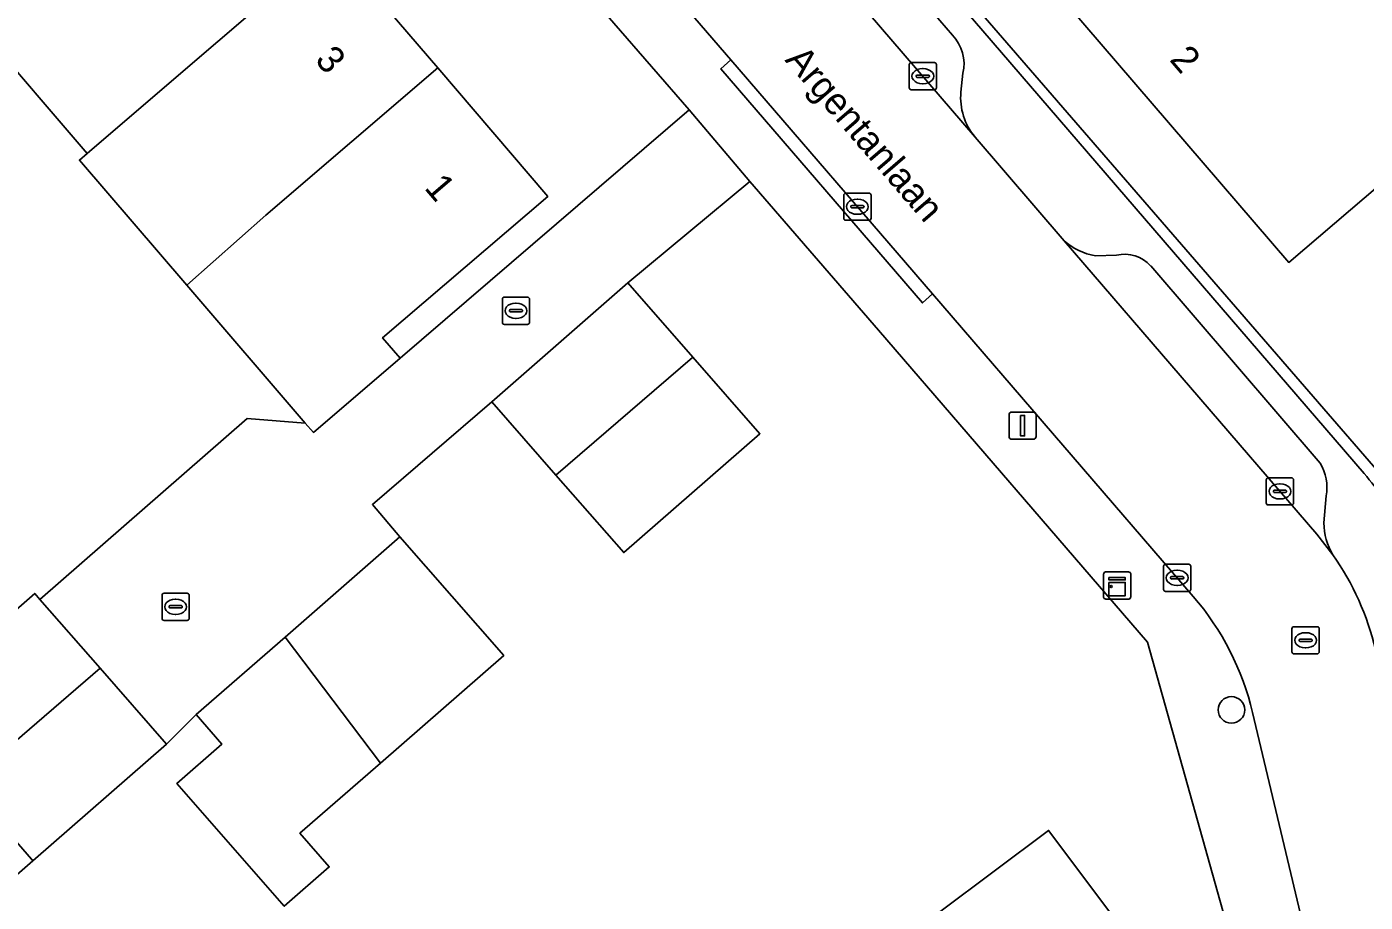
# Model space of a CAD drawing. Extents: x 158472 to 159562, y 388525 to 389606.
# Drawn here: x 159119.07 to 159168.29, y 388962.68 to 388994.9 of the extents above; entities that cross this region are included whole.
import ezdxf

# ---------------------------------------------------------------- set-up
doc = ezdxf.new("R2010")
doc.units = 0
for name, color, linetype in [('IMGEO_Boom', 7, 'Continuous'), ('IMGEO_Erf', 7, 'Continuous'), ('IMGEO_Groenvoorziening', 7, 'Continuous'), ('IMGEO_Kast', 7, 'Continuous'), ('IMGEO_Kolk', 7, 'Continuous'), ('IMGEO_Lichtmast', 7, 'Continuous'), ('IMGEO_Muur', 7, 'Continuous'), ('IMGEO_Openbare_ruimte_label', 7, 'Continuous'), ('IMGEO_Pand', 7, 'Continuous'), ('IMGEO_Pand_nummerreeks', 7, 'Continuous'), ('IMGEO_Parkeervlak_open', 7, 'Continuous'), ('IMGEO_Rijbaan_lokaal_open', 7, 'Continuous'), ('IMGEO_Rioolput', 7, 'Continuous'), ('IMGEO_Voetpad_open', 7, 'Continuous')]:
    doc.layers.add(name, color=color, linetype=linetype)

msp = doc.modelspace()

# ---------------------------------------------------------------- linework, layer by layer
at = {"layer": 'IMGEO_Boom'}
msp.add_circle((159163.368, 388969.761), 0.489, dxfattribs=at)
at = {"layer": 'IMGEO_Erf'}
for points in [[(159118.567, 389011.629), (159120.859, 389008.951), (159122.471, 389007.068), (159124.172, 389005.081), (159126.372, 389002.51), (159128.521, 389000), (159128.666, 388999.83), (159130.274, 388997.952), (159131.979, 388995.96), (159134.177, 388993.391), (159138.228, 388988.659), (159132.151, 388983.457), (159132.794, 388982.706), (159143.43, 388991.84), (159136.496, 388999.827), (159136.348, 389000), (159133.184, 389003.697), (159128.667, 389008.929), (159125.355, 389012.799), (159120.867, 389018.029), (159119.175, 389020.005)], [(159114.455, 388969.768), (159119.356, 388974.048), (159119.547, 388973.829), (159127.165, 388980.484), (159129.309, 388980.318), (159124.951, 388985.395), (159121.003, 388989.994), (159121.284, 388990.235), (159117.383, 388994.78)], [(159164.945, 388955.64), (159162.862, 388963.067), (159160.285, 388972.252), (159150.387, 388983.731), (159145.661, 388989.212), (159141.174, 388985.475), (159143.562, 388982.741), (159146.025, 388979.921), (159141.02, 388975.55), (159138.527, 388978.405), (159136.169, 388981.104), (159131.778, 388977.318), (159132.791, 388976.129), (159136.604, 388971.764), (159132.069, 388967.803), (159129.112, 388965.22), (159130.191, 388963.985), (159128.535, 388962.538), (159124.587, 388967.056), (159126.243, 388968.503), (159125.295, 388969.587), (159124.199, 388968.503), (159119.287, 388964.213), (159114.314, 388959.869)], [(159152.647, 388962.327), (159156.646, 388965.327), (159161.636, 388958.674)]]:
    msp.add_lwpolyline(points, dxfattribs=at)
at = {"layer": 'IMGEO_Groenvoorziening'}
for points in [[(159153.445, 388996.248), (159153.16, 388996.004), (159168.248, 388978.456)], [(159169.627, 388976.586), (159170.096, 388976.988), (159153.445, 388996.248)]]:
    msp.add_lwpolyline(points, dxfattribs=at)
msp.add_arc((159156.207, 388968.133), 15.861, 32.2058, 40.6068, dxfattribs=at)
at = {"layer": 'IMGEO_Kast'}
for p, q in [((159158.666, 388973.914), (159158.666, 388974.755)), ((159158.666, 388974.755), (159158.666, 388973.914)), ((159158.741, 388974.839), (159159.582, 388974.839)), ((159159.582, 388974.839), (159158.741, 388974.839)), ((159159.666, 388974.764), (159159.666, 388973.923)), ((159159.666, 388973.923), (159159.666, 388974.764)), ((159159.591, 388973.839), (159158.75, 388973.839)), ((159158.75, 388973.839), (159159.591, 388973.839))]:
    msp.add_line(p, q, dxfattribs=at)
for points in [[(159158.861, 388974.629), (159159.461, 388974.629), (159159.461, 388974.544), (159158.861, 388974.544), (159158.861, 388974.629)], [(159158.861, 388974.454), (159159.461, 388974.454), (159159.461, 388973.965), (159158.861, 388973.965), (159158.861, 388974.454)]]:
    msp.add_lwpolyline(points, dxfattribs=at)
msp.add_circle((159158.945, 388974.303), 0.0377, dxfattribs=at)
for centre, start, end in [((159158.744, 388974.761), 92.4484, 184.2845), ((159158.744, 388974.761), 92.4484, 184.2845), ((159159.588, 388974.761), 2.4484, 94.2845), ((159159.588, 388974.761), 2.4484, 94.2845), ((159158.744, 388973.917), 182.4484, 274.2845), ((159158.744, 388973.917), 182.4484, 274.2845), ((159159.588, 388973.917), 272.4484, 4.2845), ((159159.588, 388973.917), 272.4484, 4.2845)]:
    msp.add_arc(centre, 0.0779, start, end, dxfattribs=at)
at = {"layer": 'IMGEO_Kolk'}
for p, q in [((159151.519, 388992.654), (159151.519, 388993.506)), ((159151.594, 388993.58), (159152.446, 388993.58)), ((159152.007, 388993.36), (159152.032, 388993.36)), ((159152.52, 388993.506), (159152.52, 388992.654)), ((159151.778, 388993.074), (159151.778, 388993.086)), ((159152.216, 388993.037), (159151.818, 388993.037)), ((159151.821, 388993.123), (159152.219, 388993.123)), ((159152.03, 388992.8), (159152.005, 388992.8)), ((159152.262, 388993.086), (159152.262, 388993.074)), ((159152.446, 388992.58), (159151.594, 388992.58)), ((159149.113, 388987.853), (159149.113, 388988.705)), ((159149.188, 388988.779), (159150.04, 388988.779)), ((159149.415, 388988.322), (159149.813, 388988.322)), ((159149.601, 388988.559), (159149.626, 388988.559)), ((159150.114, 388988.705), (159150.114, 388987.853)), ((159149.372, 388988.273), (159149.372, 388988.285)), ((159149.81, 388988.236), (159149.412, 388988.236)), ((159149.624, 388987.999), (159149.599, 388987.999)), ((159149.856, 388988.285), (159149.856, 388988.273)), ((159150.04, 388987.779), (159149.188, 388987.779)), ((159136.555, 388984.024), (159136.555, 388984.876)), ((159136.63, 388984.95), (159137.482, 388984.95)), ((159137.556, 388984.876), (159137.556, 388984.024)), ((159136.814, 388984.444), (159136.814, 388984.456)), ((159137.252, 388984.407), (159136.854, 388984.407)), ((159136.857, 388984.493), (159137.255, 388984.493)), ((159137.043, 388984.73), (159137.068, 388984.73)), ((159137.298, 388984.456), (159137.298, 388984.444)), ((159137.482, 388983.95), (159136.63, 388983.95)), ((159137.066, 388984.17), (159137.041, 388984.17)), ((159164.651, 388977.377), (159164.651, 388978.229)), ((159164.726, 388978.303), (159165.578, 388978.303)), ((159165.139, 388978.083), (159165.164, 388978.083)), ((159165.652, 388978.229), (159165.652, 388977.377)), ((159164.91, 388977.797), (159164.91, 388977.809)), ((159165.348, 388977.76), (159164.95, 388977.76)), ((159164.953, 388977.846), (159165.351, 388977.846)), ((159165.162, 388977.523), (159165.137, 388977.523)), ((159165.394, 388977.809), (159165.394, 388977.797)), ((159165.578, 388977.303), (159164.726, 388977.303)), ((159160.872, 388974.196), (159160.872, 388975.048)), ((159160.947, 388975.122), (159161.799, 388975.122)), ((159161.873, 388975.048), (159161.873, 388974.196)), ((159161.131, 388974.616), (159161.131, 388974.628)), ((159161.569, 388974.579), (159161.171, 388974.579)), ((159161.174, 388974.665), (159161.572, 388974.665)), ((159161.36, 388974.902), (159161.385, 388974.902)), ((159161.615, 388974.628), (159161.615, 388974.616)), ((159124.114, 388974.056), (159124.966, 388974.056)), ((159161.799, 388974.122), (159160.947, 388974.122)), ((159161.383, 388974.342), (159161.358, 388974.342)), ((159124.039, 388973.13), (159124.039, 388973.982)), ((159124.298, 388973.55), (159124.298, 388973.562)), ((159124.341, 388973.599), (159124.739, 388973.599)), ((159124.527, 388973.836), (159124.552, 388973.836)), ((159124.782, 388973.562), (159124.782, 388973.55)), ((159125.04, 388973.982), (159125.04, 388973.13)), ((159124.966, 388973.056), (159124.114, 388973.056)), ((159124.736, 388973.513), (159124.338, 388973.513)), ((159124.55, 388973.276), (159124.525, 388973.276))]:
    msp.add_line(p, q, dxfattribs=at)
for points in [[(159151.519, 388992.654), (159151.519, 388993.506)], [(159151.594, 388993.58), (159152.446, 388993.58)], [(159152.52, 388993.506), (159152.52, 388992.654)], [(159152.446, 388992.58), (159151.594, 388992.58)], [(159149.113, 388987.853), (159149.113, 388988.705)], [(159149.188, 388988.779), (159150.04, 388988.779)], [(159150.114, 388988.705), (159150.114, 388987.853)], [(159150.04, 388987.779), (159149.188, 388987.779)], [(159136.555, 388984.024), (159136.555, 388984.876)], [(159136.63, 388984.95), (159137.482, 388984.95)], [(159137.556, 388984.876), (159137.556, 388984.024)], [(159137.482, 388983.95), (159136.63, 388983.95)], [(159164.651, 388977.377), (159164.651, 388978.229)], [(159164.726, 388978.303), (159165.578, 388978.303)], [(159165.652, 388978.229), (159165.652, 388977.377)], [(159165.578, 388977.303), (159164.726, 388977.303)], [(159160.872, 388974.196), (159160.872, 388975.048)], [(159160.947, 388975.122), (159161.799, 388975.122)], [(159161.873, 388975.048), (159161.873, 388974.196)], [(159124.114, 388974.056), (159124.966, 388974.056)], [(159161.799, 388974.122), (159160.947, 388974.122)], [(159124.039, 388973.13), (159124.039, 388973.982)], [(159125.04, 388973.982), (159125.04, 388973.13)], [(159124.966, 388973.056), (159124.114, 388973.056)]]:
    msp.add_lwpolyline(points, dxfattribs=at)
for centre, radius, start, end in [((159151.596, 388993.504), 0.0765, 91.552, 178.448), ((159151.596, 388993.504), 0.0765, 91.552, 178.448), ((159152.444, 388993.504), 0.0765, 1.552, 88.448), ((159152.444, 388993.504), 0.0765, 1.552, 88.448), ((159151.818, 388993.083), 0.0403, 85.8775, 175.7526), ((159151.815, 388993.073), 0.0366, 178.938, 274.7102), ((159152.219, 388993.08), 0.043, 264.8664, 352.4533), ((159152.223, 388993.085), 0.0386, 1.7309, 96.639), ((159151.596, 388992.656), 0.0765, 181.552, 268.448), ((159151.596, 388992.656), 0.0765, 181.552, 268.448), ((159152.444, 388992.656), 0.0765, 271.552, 358.448), ((159152.444, 388992.656), 0.0765, 271.552, 358.448), ((159149.19, 388988.703), 0.0765, 91.552, 178.448), ((159149.19, 388988.703), 0.0765, 91.552, 178.448), ((159149.412, 388988.282), 0.0403, 85.8775, 175.7526), ((159149.817, 388988.284), 0.0386, 1.7309, 96.639), ((159150.038, 388988.703), 0.0765, 1.552, 88.448), ((159150.038, 388988.703), 0.0765, 1.552, 88.448), ((159149.19, 388987.855), 0.0765, 181.552, 268.448), ((159149.19, 388987.855), 0.0765, 181.552, 268.448), ((159149.409, 388988.272), 0.0366, 178.938, 274.7102), ((159149.813, 388988.279), 0.043, 264.8664, 352.4533), ((159150.038, 388987.855), 0.0765, 271.552, 358.448), ((159150.038, 388987.855), 0.0765, 271.552, 358.448), ((159136.632, 388984.874), 0.0765, 91.552, 178.448), ((159136.632, 388984.874), 0.0765, 91.552, 178.448), ((159137.48, 388984.874), 0.0765, 1.552, 88.448), ((159137.48, 388984.874), 0.0765, 1.552, 88.448), ((159136.854, 388984.453), 0.0403, 85.8775, 175.7526), ((159136.851, 388984.443), 0.0366, 178.938, 274.7102), ((159137.255, 388984.45), 0.043, 264.8664, 352.4533), ((159137.259, 388984.455), 0.0386, 1.7309, 96.639), ((159136.632, 388984.026), 0.0765, 181.552, 268.448), ((159136.632, 388984.026), 0.0765, 181.552, 268.448), ((159137.48, 388984.026), 0.0765, 271.552, 358.448), ((159137.48, 388984.026), 0.0765, 271.552, 358.448), ((159164.728, 388978.227), 0.0765, 91.552, 178.448), ((159164.728, 388978.227), 0.0765, 91.552, 178.448), ((159165.576, 388978.227), 0.0765, 1.552, 88.448), ((159165.576, 388978.227), 0.0765, 1.552, 88.448), ((159164.95, 388977.806), 0.0403, 85.8775, 175.7526), ((159164.947, 388977.796), 0.0366, 178.938, 274.7102), ((159165.351, 388977.803), 0.043, 264.8664, 352.4533), ((159165.355, 388977.808), 0.0386, 1.7309, 96.639), ((159164.728, 388977.379), 0.0765, 181.552, 268.448), ((159164.728, 388977.379), 0.0765, 181.552, 268.448), ((159165.576, 388977.379), 0.0765, 271.552, 358.448), ((159165.576, 388977.379), 0.0765, 271.552, 358.448), ((159160.949, 388975.046), 0.0765, 91.552, 178.448), ((159160.949, 388975.046), 0.0765, 91.552, 178.448), ((159161.797, 388975.046), 0.0765, 1.552, 88.448), ((159161.797, 388975.046), 0.0765, 1.552, 88.448), ((159161.171, 388974.625), 0.0403, 85.8775, 175.7526), ((159161.168, 388974.615), 0.0366, 178.938, 274.7102), ((159161.572, 388974.622), 0.043, 264.8664, 352.4533), ((159161.576, 388974.627), 0.0386, 1.7309, 96.639), ((159124.116, 388973.98), 0.0765, 91.552, 178.448), ((159124.116, 388973.98), 0.0765, 91.552, 178.448), ((159124.964, 388973.98), 0.0765, 1.552, 88.448), ((159124.964, 388973.98), 0.0765, 1.552, 88.448), ((159160.949, 388974.198), 0.0765, 181.552, 268.448), ((159160.949, 388974.198), 0.0765, 181.552, 268.448), ((159161.797, 388974.198), 0.0765, 271.552, 358.448), ((159161.797, 388974.198), 0.0765, 271.552, 358.448), ((159124.338, 388973.559), 0.0403, 85.8775, 175.7526), ((159124.335, 388973.549), 0.0366, 178.938, 274.7102), ((159124.739, 388973.556), 0.043, 264.8664, 352.4533), ((159124.743, 388973.561), 0.0386, 1.7309, 96.639), ((159124.116, 388973.132), 0.0765, 181.552, 268.448), ((159124.116, 388973.132), 0.0765, 181.552, 268.448), ((159124.964, 388973.132), 0.0765, 271.552, 358.448), ((159124.964, 388973.132), 0.0765, 271.552, 358.448)]:
    msp.add_arc(centre, radius, start, end, dxfattribs=at)
for centre, major_axis, ratio, start_param, end_param in [((159152.006, 388993.08), (-0.387, 0.002), 0.722429, 4.712389, 7.853982), ((159152.031, 388993.08), (-0.39, 0.002), 0.717154, 1.570796, 4.712389), ((159149.6, 388988.279), (-0.387, 0.002), 0.722429, 4.712389, 7.853982), ((159149.625, 388988.279), (-0.39, 0.002), 0.717154, 1.570796, 4.712389), ((159137.042, 388984.45), (-0.387, 0.002), 0.722429, 4.712389, 7.853982), ((159137.067, 388984.45), (-0.39, 0.002), 0.717154, 1.570796, 4.712389), ((159165.138, 388977.803), (-0.387, 0.002), 0.722429, 4.712389, 7.853982), ((159165.163, 388977.803), (-0.39, 0.002), 0.717154, 1.570796, 4.712389), ((159161.359, 388974.622), (-0.387, 0.002), 0.722429, 4.712389, 7.853982), ((159161.384, 388974.622), (-0.39, 0.002), 0.717154, 1.570796, 4.712389), ((159124.526, 388973.556), (-0.387, 0.002), 0.722429, 4.712389, 7.853982), ((159124.551, 388973.556), (-0.39, 0.002), 0.717154, 1.570796, 4.712389)]:
    msp.add_ellipse(centre, major_axis=major_axis, ratio=ratio, start_param=start_param, end_param=end_param, dxfattribs=at)
at = {"layer": 'IMGEO_Lichtmast'}
for p, q in [((159155.192, 388979.822), (159155.192, 388980.622)), ((159155.192, 388980.622), (159155.192, 388979.822)), ((159155.292, 388980.722), (159156.082, 388980.722)), ((159156.082, 388980.722), (159155.292, 388980.722)), ((159156.182, 388980.622), (159156.182, 388979.822)), ((159156.182, 388979.822), (159156.182, 388980.622)), ((159156.082, 388979.722), (159155.292, 388979.722)), ((159155.292, 388979.722), (159156.082, 388979.722))]:
    msp.add_line(p, q, dxfattribs=at)
msp.add_lwpolyline([(159155.612, 388980.597), (159155.762, 388980.597), (159155.762, 388979.847), (159155.612, 388979.847), (159155.612, 388980.597)], dxfattribs=at)
for centre, start, end in [((159155.292, 388980.622), 90, 180), ((159155.292, 388980.622), 90, 180), ((159156.082, 388980.622), 0, 90), ((159156.082, 388980.622), 360, 90), ((159155.292, 388979.822), 180, 270), ((159155.292, 388979.822), 180, 270), ((159156.082, 388979.822), 270, 0), ((159156.082, 388979.822), 270, 0)]:
    msp.add_arc(centre, 0.1, start, end, dxfattribs=at)
at = {"layer": 'IMGEO_Muur'}
for points in [[(159150.387, 388983.731), (159160.285, 388972.252), (159162.862, 388963.067)], [(159129.309, 388980.318), (159127.165, 388980.484), (159119.547, 388973.829)]]:
    msp.add_lwpolyline(points, dxfattribs=at)
at = {"layer": 'IMGEO_Pand'}
for points in [[(159203.019, 389018.342), (159193.124, 389029.895), (159192.975, 389030.069), (159172.865, 389012.863), (159155.422, 388997.939), (159165.476, 388986.23), (159177.236, 388996.288)], [(159130.274, 388997.952), (159128.666, 388999.83), (159128.521, 389000), (159126.372, 389002.51), (159123.454, 389000), (159120.061, 388997.082), (159117.663, 388995.021), (159117.383, 388994.78), (159121.284, 388990.235), (159123.957, 388992.53)], [(159134.177, 388993.391), (159131.979, 388995.96), (159130.274, 388997.952), (159123.957, 388992.53), (159121.284, 388990.235), (159121.003, 388989.994), (159124.951, 388985.395), (159127.857, 388987.973)], [(159127.857, 388987.973), (159124.951, 388985.395), (159129.309, 388980.318), (159129.608, 388979.97), (159132.794, 388982.706), (159132.151, 388983.457), (159138.228, 388988.659), (159134.177, 388993.391)], [(159138.527, 388978.405), (159143.55, 388982.73), (159143.562, 388982.741), (159141.174, 388985.475), (159136.169, 388981.104)], [(159138.527, 388978.405), (159141.02, 388975.55), (159146.025, 388979.921), (159143.562, 388982.741), (159143.55, 388982.73)], [(159128.564, 388972.44), (159132.069, 388967.803), (159136.604, 388971.764), (159132.791, 388976.129)], [(159114.455, 388969.768), (159116.82, 388967.04), (159121.759, 388971.296), (159119.547, 388973.829), (159119.356, 388974.048)], [(159128.564, 388972.44), (159125.295, 388969.587), (159126.243, 388968.503), (159124.587, 388967.056), (159128.535, 388962.538), (159130.191, 388963.985), (159129.112, 388965.22), (159132.069, 388967.803)], [(159116.82, 388967.04), (159119.24, 388964.27), (159119.287, 388964.213), (159124.199, 388968.503), (159121.759, 388971.296)], [(159116.82, 388967.04), (159111.816, 388962.729), (159114.016, 388960.211), (159114.314, 388959.869), (159119.287, 388964.213), (159119.24, 388964.27)], [(159151.75, 388961.654), (159156.74, 388955.002), (159161.636, 388958.674), (159156.646, 388965.327), (159152.647, 388962.327)]]:
    msp.add_lwpolyline(points, close=True, dxfattribs=at)
at = {"layer": 'IMGEO_Parkeervlak_open'}
for points in [[(159143.71, 389002.747), (159146.071, 389000), (159153.949, 388990.832)], [(159153.106, 388994.586), (159148.455, 389000), (159147.111, 389001.564)], [(159153.42, 388992.498), (159153.493, 388993.192)], [(159157.221, 388987.027), (159166.505, 388976.226), (159167.097, 388975.467)], [(159159.147, 388986.497), (159158.367, 388986.473)], [(159166.636, 388978.847), (159160.399, 388986.103)], [(159166.772, 388976.642), (159166.854, 388977.635)]]:
    msp.add_lwpolyline(points, dxfattribs=at)
for centre, radius, start, end in [((159152.044, 388993.54), 1.49, 346.4825, 44.5488), ((159155.661, 388992.293), 2.251, 174.7642, 220.4679), ((159158.755, 388988.738), 2.298, 228.1198, 260.28), ((159159.432, 388985.218), 1.31, 42.4799, 102.5829), ((159165.049, 388977.936), 1.83, 350.5332, 29.8601), ((159169.062, 388976.643), 2.29, 180.0233, 210.8992)]:
    msp.add_arc(centre, radius, start, end, dxfattribs=at)
at = {"layer": 'IMGEO_Rijbaan_lokaal_open'}
for points in [[(159157.221, 388987.027), (159153.949, 388990.832), (159146.071, 389000), (159143.71, 389002.747), (159140.367, 389006.639), (159130.603, 389018.005), (159126.851, 389022.373), (159123.771, 389025.812), (159121.896, 389024.199), (159120.042, 389022.605), (159120.134, 389022.499), (159123.157, 389018.99), (159126.435, 389015.185), (159131.375, 389009.452), (159134.616, 389005.691), (159139.07, 389000.521), (159139.519, 389000), (159144.963, 388993.679), (159152.379, 388985.068), (159161.965, 388973.937)], [(159167.097, 388975.467), (159166.505, 388976.226), (159157.221, 388987.027)], [(159164.149, 388969.661), (159167.138, 388957.09)]]:
    msp.add_lwpolyline(points, dxfattribs=at)
msp.add_lwpolyline([(159119.547, 388973.829), (159121.759, 388971.296), (159124.199, 388968.503), (159125.295, 388969.587), (159128.564, 388972.44), (159132.791, 388976.129), (159131.778, 388977.318), (159136.169, 388981.104), (159141.174, 388985.475), (159145.661, 388989.212), (159143.43, 388991.84), (159132.794, 388982.706), (159129.608, 388979.97), (159129.309, 388980.318), (159127.165, 388980.484)], close=True, dxfattribs=at)
for centre, radius, start, end in [((159158.862, 388969.662), 10.076, 13.3314, 35.1816), ((159154.289, 388967.32), 10.134, 13.3529, 40.7592)]:
    msp.add_arc(centre, radius, start, end, dxfattribs=at)
at = {"layer": 'IMGEO_Rioolput'}
for p, q in [((159165.595, 388971.898), (159165.595, 388972.75)), ((159165.67, 388972.824), (159166.522, 388972.824)), ((159166.083, 388972.604), (159166.108, 388972.604)), ((159166.596, 388972.75), (159166.596, 388971.898)), ((159165.854, 388972.318), (159165.854, 388972.33)), ((159166.292, 388972.281), (159165.894, 388972.281)), ((159165.897, 388972.367), (159166.295, 388972.367)), ((159166.338, 388972.33), (159166.338, 388972.318)), ((159166.522, 388971.824), (159165.67, 388971.824)), ((159166.106, 388972.044), (159166.081, 388972.044))]:
    msp.add_line(p, q, dxfattribs=at)
for points in [[(159165.595, 388971.898), (159165.595, 388972.75)], [(159165.67, 388972.824), (159166.522, 388972.824)], [(159166.596, 388972.75), (159166.596, 388971.898)], [(159166.522, 388971.824), (159165.67, 388971.824)]]:
    msp.add_lwpolyline(points, dxfattribs=at)
for centre, radius, start, end in [((159165.672, 388972.748), 0.0765, 91.552, 178.448), ((159165.672, 388972.748), 0.0765, 91.552, 178.448), ((159166.52, 388972.748), 0.0765, 1.552, 88.448), ((159166.52, 388972.748), 0.0765, 1.552, 88.448), ((159165.894, 388972.327), 0.0403, 85.8775, 175.7526), ((159165.891, 388972.317), 0.0366, 178.938, 274.7102), ((159166.295, 388972.324), 0.043, 264.8664, 352.4533), ((159166.299, 388972.329), 0.0386, 1.7309, 96.639), ((159165.672, 388971.9), 0.0765, 181.552, 268.448), ((159165.672, 388971.9), 0.0765, 181.552, 268.448), ((159166.52, 388971.9), 0.0765, 271.552, 358.448), ((159166.52, 388971.9), 0.0765, 271.552, 358.448)]:
    msp.add_arc(centre, radius, start, end, dxfattribs=at)
for centre, major_axis, ratio, start_param, end_param in [((159166.082, 388972.324), (-0.387, 0.002), 0.722429, 4.712389, 7.853982), ((159166.107, 388972.324), (-0.39, 0.002), 0.717154, 1.570796, 4.712389)]:
    msp.add_ellipse(centre, major_axis=major_axis, ratio=ratio, start_param=start_param, end_param=end_param, dxfattribs=at)
at = {"layer": 'IMGEO_Voetpad_open'}
for points in [[(159190.74, 388994.674), (159185.794, 389000.379), (159191.537, 389005.315), (159196.479, 388999.591), (159198.681, 389001.477), (159211.761, 389012.659), (159218.479, 389018.411), (159220.227, 389019.907), (159220.057, 389020.924), (159219.946, 389021.639), (159218.174, 389020.125), (159210.843, 389013.865), (159204.025, 389021.804), (159202.023, 389024.136), (159199.862, 389026.653), (159198.136, 389028.662), (159195.411, 389031.836), (159193.124, 389029.895), (159203.019, 389018.342), (159177.236, 388996.288), (159165.476, 388986.23), (159155.422, 388997.939), (159153.445, 388996.248), (159170.096, 388976.988)], [(159144.963, 388993.679), (159144.585, 388993.352), (159152.001, 388984.741), (159152.379, 388985.068)]]:
    msp.add_lwpolyline(points, close=True, dxfattribs=at)
for points in [[(159168.248, 388978.456), (159153.16, 388996.004), (159151.36, 388998.098), (159149.725, 389000), (159141.471, 389009.601), (159135.248, 389016.839), (159125.639, 389027.992)], [(159161.965, 388973.937), (159152.379, 388985.068), (159152.001, 388984.741), (159144.585, 388993.352), (159144.963, 388993.679), (159139.519, 389000), (159139.07, 389000.521), (159138.693, 389000.194), (159134.239, 389005.364), (159134.616, 389005.691), (159131.375, 389009.452), (159130.998, 389009.125), (159126.058, 389014.858), (159126.435, 389015.185), (159123.157, 389018.99), (159122.779, 389018.663), (159119.756, 389022.172)], [(159119.175, 389020.005), (159120.867, 389018.029), (159125.355, 389012.799), (159128.667, 389008.929), (159133.184, 389003.697), (159136.348, 389000), (159136.496, 388999.827), (159143.43, 388991.84), (159145.661, 388989.212), (159150.387, 388983.731), (159160.285, 388972.252), (159162.862, 388963.067), (159164.945, 388955.64), (159167.138, 388957.09), (159164.149, 388969.661)], [(159147.111, 389001.564), (159148.455, 389000), (159153.106, 388994.586)], [(159153.493, 388993.192), (159153.42, 388992.498)], [(159153.949, 388990.832), (159157.221, 388987.027)], [(159158.367, 388986.473), (159159.147, 388986.497)], [(159160.399, 388986.103), (159166.636, 388978.847)], [(159166.854, 388977.635), (159166.772, 388976.642)]]:
    msp.add_lwpolyline(points, dxfattribs=at)
for centre, radius, start, end in [((159152.044, 388993.54), 1.49, 346.4825, 44.5488), ((159155.661, 388992.293), 2.251, 174.7642, 220.4679), ((159158.755, 388988.738), 2.298, 228.1198, 260.28), ((159159.432, 388985.218), 1.31, 42.4799, 102.5829), ((159165.049, 388977.936), 1.83, 350.5332, 29.8601), ((159156.207, 388968.133), 15.861, 32.2058, 40.6068), ((159169.062, 388976.643), 2.29, 180.0233, 210.8992), ((159158.862, 388969.662), 10.076, 13.3314, 35.1816), ((159154.289, 388967.32), 10.134, 13.3529, 40.7592)]:
    msp.add_arc(centre, radius, start, end, dxfattribs=at)

# ---------------------------------------------------------------- texts
at = {"layer": 'IMGEO_Openbare_ruimte_label'}
msp.add_text('Argentanlaan', height=1, rotation=310.7442, dxfattribs=at).set_placement((159146.92, 388993.663))
at = {"layer": 'IMGEO_Pand_nummerreeks'}
for s, rotation, p in [('3', 310.5595, (159129.629, 388993.661)), ('2', 310.6511, (159161.061, 388993.675)), ('1', 310.561, (159133.656, 388988.958))]:
    msp.add_text(s, height=1, rotation=rotation, dxfattribs=at).set_placement(p)

doc.saveas('drawing.dxf')
